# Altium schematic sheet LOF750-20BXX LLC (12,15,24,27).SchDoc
size A4; Revision: A; SheetNumber: 1; SheetTotal: 1
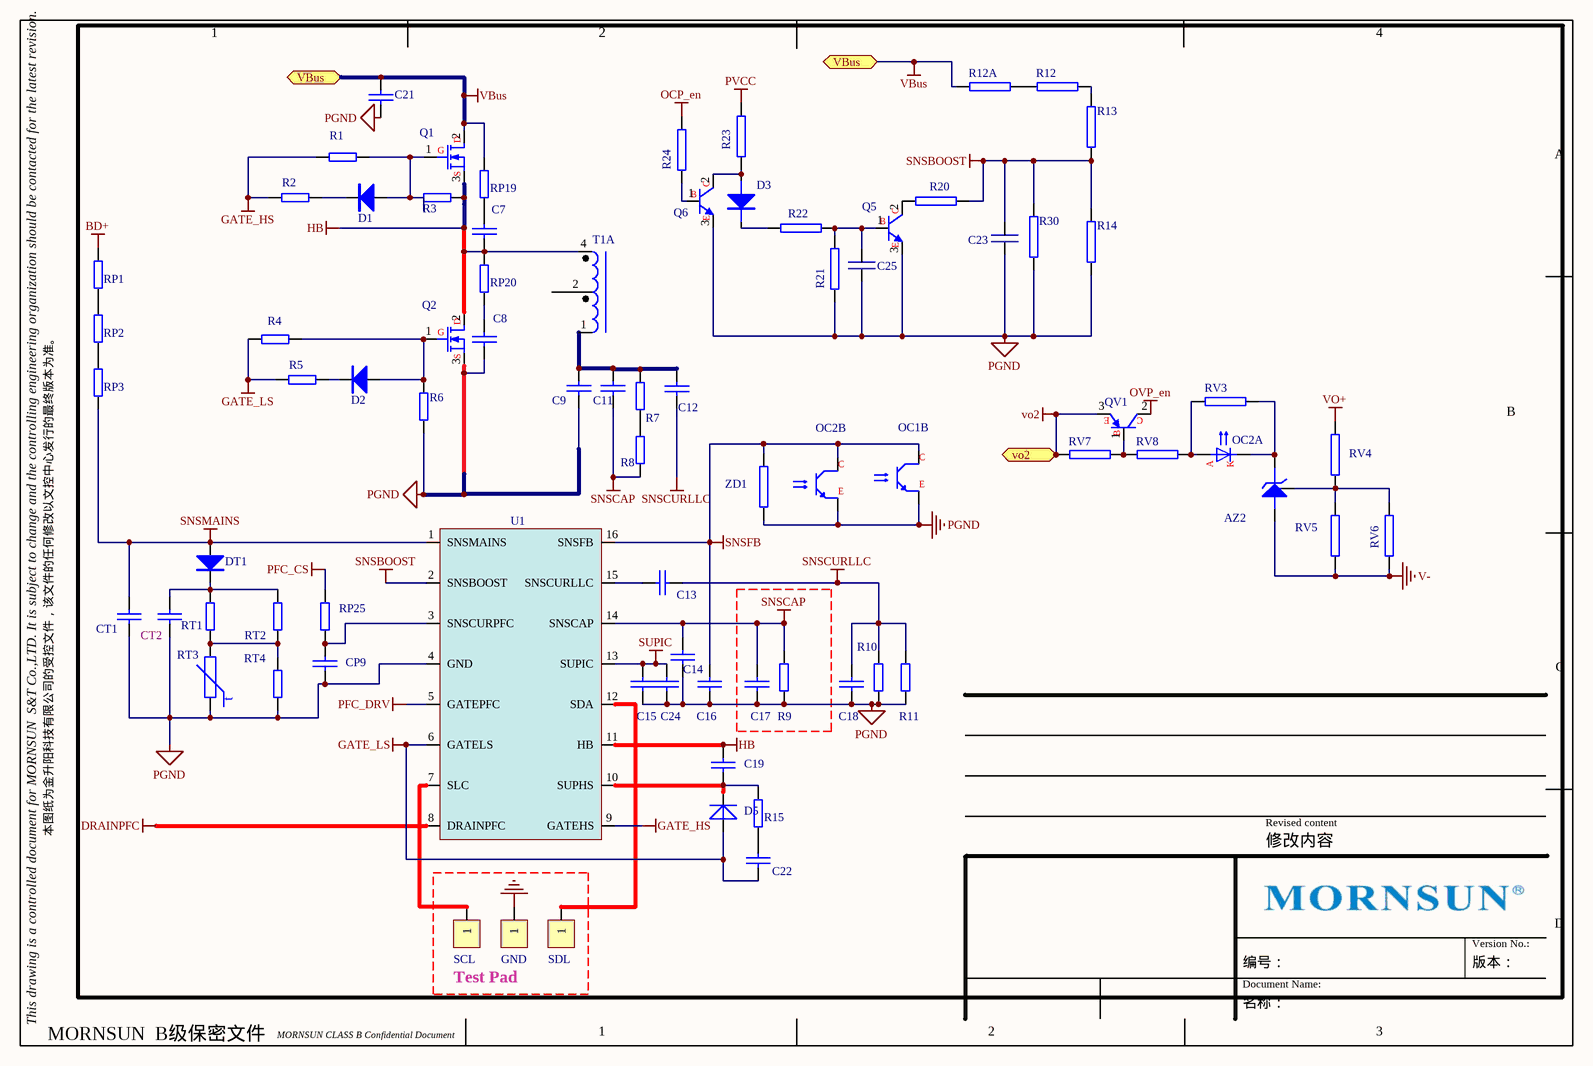
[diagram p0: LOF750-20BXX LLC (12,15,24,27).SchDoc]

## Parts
AZ2  AZ431AN  [SOT-23A]  (value not drawn)
C7  22P/2KV/1206  [SC-1206]  (value not drawn)
C8  22P/2KV/1206  [SC-1206]  (value not drawn)
C9  30050018  [CAP-15-18.0X10.0-X]  (value not drawn)
C11  33pF/1kV/1206  [SC-1206]  (value not drawn)
C12  (no value)  [SC-1206]
C13  (no value)  [SC-0603]
C14  153/50V/0603  [SC-0603]  (value not drawn)
C15  104/50V  [SC-0603]  (value not drawn)
C16  471/50V/0603  [SC-0603]  (value not drawn)
C17  153/50V/0603  [SC-0603]  (value not drawn)
C18  (no value)  [SC-0603]
C19  334/50V/0805  [SC-0805]  (value not drawn)
C21  (no value)  [SC-1206]
C22  22P/2KV/1206  [SC-1206]  (value not drawn)
C23  0603  [SC-0603]  (value not drawn)
C24  104/50V  [SC-0805]  (value not drawn)
C25  105K/16V/0603  [SC-0603]  (value not drawn)
CP9  101/100V/0603  [SC-0603]  (value not drawn)
CT1  (no value)  [SC-0603]
CT2  (no value)  [SC-0805]
D1  (no value)  [SOD-123&SD-1206]
D2  (no value)  [SOD-123&SD-1206]
D3  SOD323  [SOD-323]  (value not drawn)
D5  ES1J  [SOD-123&SD-1206]  (value not drawn)
DT1  (no value)  [SOD-323]
GND  MHDR1X1  [TES-1.5]  (value not drawn)
OC1  TCLT1008/OC  [SOPT-101]  (value not drawn)  (part B of 2)
OC2  OC  [SOPT-101]  (value not drawn)  (parts A,B of 2)
Q1  STD16N50M2  [TO220-3]  (value not drawn)
Q2  STD16N50M2  [TO220-3]  (value not drawn)
Q5  SOT-23  [SOT-23A]  (value not drawn)
Q6  SOT-23  [SOT-23A]  (value not drawn)
QV1  SOT-23  [SOT-23A]  (value not drawn)
R1  47R/1206  [SR-1206]  (value not drawn)
R2  47R/1206  [SR-1206]  (value not drawn)
R3  10K/0603  [SR-0603]  (value not drawn)
R4  47R/1206  [SR-1206]  (value not drawn)
R5  47R/1206  [SR-1206]  (value not drawn)
R6  10K/0603  [SR-0603]  (value not drawn)
R7  2.2M/1206  [SC-1206]  (value not drawn)
R8  2.2M/1206  [SC-1206]  (value not drawn)
R9  1206  [SR-0603]  (value not drawn)
R10  0603  [SR-0603]  (value not drawn)
R11  0603  [SR-0603]  (value not drawn)
R12  2M/1206  [SR-1206]  (value not drawn)
R12A  2M/1206  [SR-1206]  (value not drawn)
R13  2M/1206  [SR-1206]  (value not drawn)
R14  27K/0603  [SR-0603]  (value not drawn)
R15  47R/1206  [SR-0805]  (value not drawn)
R20  10K/0603  [SR-0603]  (value not drawn)
R21  5K/0603  [SR-0603]  (value not drawn)
R22  5K/0603  [SR-0603]  (value not drawn)
R23  100K/0603  [SR-0603]  (value not drawn)
R24  10K/0603  [SR-0603]  (value not drawn)
R30  27K/0603  [SR-0603]  (value not drawn)
RP1  510K/1206  [SR-1206]  (value not drawn)
RP2  510K/1206  [SR-1206]  (value not drawn)
RP3  510K/1206  [SR-1206]  (value not drawn)
RP19  47R/1206  [SR-1206]  (value not drawn)
RP20  47R/1206  [SR-1206]  (value not drawn)
RP25  2K/0805  [SR-0805]  (value not drawn)
RT1  97.6K/0603  [SR-0603]  (value not drawn)
RT2  97.6K/0603  [SR-0603]  (value not drawn)
RT3  RT  [TSR-2.0-3.5X2.5]  (value not drawn)
RT4  97.6K/0603  [SR-0603]  (value not drawn)
RV3  1k/0603  [SR-0603]  (value not drawn)
RV4  2.4k/0603  [SR-0603]  (value not drawn)
RV5  2.4k/0603  [SR-0603]  (value not drawn)
RV6  2.4k/0603  [SR-0603]  (value not drawn)
RV7  2K/0603  [SR-0603]  (value not drawn)
RV8  2K/0805  [SR-0805]  (value not drawn)
SCL  MHDR1X1  [TES-1.5]  (value not drawn)
SDL  MHDR1X1  [TES-1.5]  (value not drawn)
T1  PQ3535/开模  [750W-T1]  (value not drawn)  (part A of 2)
U1  TEA2016  [SOP16-1.27]  (value not drawn)
ZD1  0603  [SC-0603]  (value not drawn)

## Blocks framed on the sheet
Test Pad: GND SCL SDL

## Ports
VBus (bidir), vo2 (bidir)

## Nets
BD+: RP1.2
DRAINPFC: U1.8(DRAINPFC)
GATE_HS: R1.2 R2.2 U1.9(GATEHS)
GATE_LS: C22.1 D5.1(A) R4.2 R5.2 U1.6(GATELS)
HB: C7.2 C19.1 Q1.3(S) Q2.2(D) R3.1 RP20.1 T1.4 U1.11(HB)
OCP_en: R24.1
OVP_en: QV1.2(C)
PFC_CS: RP25.1
PFC_DRV: U1.5(GATEPFC)
PGND: C8.2 C9.2 C14.2 C15.2 C16.2 C17.2 C18.2 C21.2 C23.2 C24.2 C25.2 CP9.2 CT1.2 CT2.2 GND.1 OC1.3(E) OC2.3(E) Q2.3(S) Q5.3(E) Q6.3(E) R6.1 R9.2 R10.2 R11.2 R14.2 R21.2 R30.2 RT3.1 RT4.2 U1.4(GND) ZD1.2
PVCC: R23.1
SNSBOOST: C23.1 R13.2 R14.1 R20.2 R30.1 U1.2(SNSBOOST)
SNSCAP: C11.2 C14.1 C17.1 R8.1 R9.1 U1.14(SNSCAP)
SNSCURLLC: C12.2 C13.2 C18.1 R10.1 R11.1
SNSFB: C16.1 OC1.4(C) OC2.4(C) U1.16(SNSFB) ZD1.1
SNSMAINS: CT1.1 DT1.1(A) RP3.1 U1.1(SNSMAINS)
SUPIC: C15.1 C24.1 U1.13(SUPIC)
V-: AZ2.2 RV5.2 RV6.2
VBus: C21.1 Q1.2(D) R12A.1 RP19.1 ; port VBus
vo2: QV1.3(E) RV7.1 ; port vo2
VO+: RV4.1
NetAZ2_1: AZ2.1 RV4.2 RV5.1 RV6.1
NetAZ2_3: AZ2.3 OC2.2(K) RV3.2
NetC7_1: C7.1 RP19.2
NetC8_1: C8.1 RP20.2
NetC9_1: C9.1 C11.1 C12.1 R7.2 T1.1
NetC13_1: C13.1 U1.15(SNSCURLLC)
NetC19_2: C19.2 D5.2(K) R15.2 U1.10(SUPHS)
NetC22_2: C22.2 R15.1
NetC25_1: C25.1 Q5.1(B) R21.1 R22.2
NetCP9_1: CP9.1 RP25.2 U1.3(SNSCURPFC)
NetCT2_1: CT2.1 DT1.2(K) RT1.1 RT2.1
NetD1_1: D1.1(A) Q1.1(G) R1.1 R3.2
NetD1_2: D1.2(K) R2.1
NetD2_1: D2.1(A) Q2.1(G) R4.1 R6.2
NetD2_2: D2.2(K) R5.1
NetD3_1: D3.1(A) Q6.2(C) R23.2
NetD3_2: D3.2(K) R22.1
NetOC2_1: OC2.1(A) RV3.1 RV8.2
NetQ5_2: Q5.2(C) R20.1
NetQ6_1: Q6.1(B) R24.2
NetQV1_1: QV1.1(B) RV7.2 RV8.1
NetR7_1: R7.1 R8.2
NetR12_1: R12.1 R12A.2
NetR12_2: R12.2 R13.1
NetRP1_1: RP1.1 RP2.2
NetRP2_1: RP2.1 RP3.2
NetRT1_2: RT1.2 RT2.2 RT3.2 RT4.1
NetSCL_1: SCL.1 U1.7(SLC)
NetSDL_1: SDL.1 U1.12(SDA)

Not connected (* = marked no-connect by the designer): T1 2

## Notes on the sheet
- 1
- 2
- 4
- A
- B
- C
- 本图纸为金升阳科技有限公司的受控文件，该文件的任何修改以文控中心发行的最终版本为准。
- 修改内容
- Revised content
- D
- Document Name:
- 编号：
- Version No.:
- 版本：
- This drawing is a controlled document for MORNSUN  S&T Co.,LTD. It is subject to change and the controlling engineering organization should be contacted for the latest revision.
- MORNSUN  B级保密文件
- MORNSUN CLASS B Confidential Document
- 名称：
- 3

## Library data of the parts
AZ2 = 431: MPN: AZ431AN-ATRE1; PN: 32000001
C7-C9 C11 C14-C17 C19 C21 C22 C24 CP9 = Cap: Capacitor
C12 C13 C18 CT1 CT2 = CAP
C23 C25 = CAP-1: 105K/16V/0603/X7R; PN: 30010142
D1 D2 DT1 = DI-1
D3 = DIODE: MPN: SK110; PN: 31000046
D5 = Diode
GND SCL SDL = Pin1
OC1 = OC
Q1 Q2 = MOSFET N: Value: STF28N60M2
Q5 Q6 = NPN: NPN Transistor
QV1 = PNP: PNP Transistor
R1-R11 R15 RP1-RP3 RP19 RP20 RP25 RT1 RT2 RT4 = R
R12 R12A R13 R14 R20-R24 R30 = RES1: 150KΩ 1/10W ±1% 0603; PN: 35000049
RV3-RV8 = RES1
T1 = T
U1 = NXP-TEA2016
ZD1 = RES1: PN: 35000027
